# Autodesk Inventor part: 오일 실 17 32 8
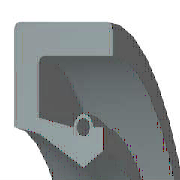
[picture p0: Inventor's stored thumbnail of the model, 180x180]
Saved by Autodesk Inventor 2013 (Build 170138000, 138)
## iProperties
IsCustomPart: 1
Created: 2012-02
Part Number: 오일 실 17 32 8
Material: 고무
Description: 오일-실
Document SubType Name: Modeling
Standard: KS B 2804
Designer: mduedu
Standards Organization: KS
Language: ko-KR
Size Designation: S - 17 32 8
Categories: <MemberInstance><Categories><Category DisplayName="샤프트 부품" InternalName="7f7aeb1f-a693-4053-b835-cee3144e0d98" Mnemonic="SHFT"><Category DisplayName="실링" Intern
Density: 0.93 g/cm^3
Mass: 1.89534 g
Surface Area: 30.829 cm^2
Volume: 2.038 cm^3
Author: mduedu
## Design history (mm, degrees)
revolve "본체" stored, may be unused: angle "d17" = 90 deg
revolve "스프링1" stored, may be unused: angle "d18" = 90 deg
body "Solid1"
sketch "스케치1"
  geometry: L1 (0, 16)-(8, 16); L2 (8, 16)-(8, 14.75); L3 (8, 14.75)-(1.75, 14.75); L4 (0, 16)-(0, 10.6); L5 (0, 10.6)-(1.75, 10.25); L6 (1.75, 10.25)-(4.9, 8.5); L7 (4.9, 8.5)-(0, 8.5); L8 (6.3, 9.375)-(6.3, 10.6); L9 (0, 0)-(9.586, 0) reference; L10 (4.9, 8.5)-(6.3, 9.375); L11 (0, 18)-(0, -3) reference; L12 (-1.917, 0)-(11.503, 0) reference; L13 (4.2, 10.6)-(1.75, 11.09); L14 (1.75, 11.09)-(1.75, 14.75); L15 (6.3, 10.6)-(5.6, 10.6); C1 r 0.455 at (4.9, 10.6); A1 r 0.7 centre (4.9, 10.6) between (5.6, 10.6) and (4.2, 10.6)
  constraints: 26 end point, 5 horizontal alignment, 4 perpendicular, 2 centre point, 2 collinear, 2 horizontal, 2 parallel, 2 point on circle, 2 point on line, 2 vertical alignment, 1 coincident
  dimensions: "d0" = 32 diameter of L1 L9 (= SD2); "d1" = 18.75 diameter of L8.start L9 (= ABDM); "d2" = 1.25 distance of L1.end L2.end (computed from SD); "d3" = 0.91 diameter of C1 (= SPDI); "d4" = 1.4 diameter of A1 (= SPDA); "d5" = 17 diameter of L6.end L9 (= NND); "d6" = 20.5 diameter of L5.end L9 (= TKDM); "d7" = 21.2 diameter of L4.end L9 (= HLDM); "d8" = 4.9 distance from line of C1.centre L4 (= SPDST); "d9" = 6.3 distance between parallel lines of L8 L4 (= SDI); "d10" = 8 distance between parallel lines of L2 L4 (= SWDT); "d12" = 1.75 distance between parallel lines of L14 L4 (= SD)
fillet "모깎기1" dims "d11" = 0.3 (= RR)
other parameters: "SD2" = 32 [user parameter; used in 1 equation term], "SWDT" = 8 [user parameter; used in 1 equation term], "RR" = 0.3 [user parameter; used in 1 equation term], "SD" = 1.75 [user parameter; used in 2 equation terms], "NND" = 17 [user parameter; used in 1 equation term], "SPDA" = 1.4 [user parameter; used in 1 equation term], "SPDI" = 0.91 [user parameter; used in 1 equation term], "TKDM" = 20.5 [user parameter; used in 1 equation term], "HLDM" = 21.2 [user parameter; used in 1 equation term], "ABDM" = 18.75 [user parameter; used in 1 equation term], "SDI" = 6.3 [user parameter; used in 1 equation term], "SPDST" = 4.9 [user parameter; used in 1 equation term], "d13" = 0, "d14" = 0, "d15" = 0, "LAB" = 0.35 [user parameter]
